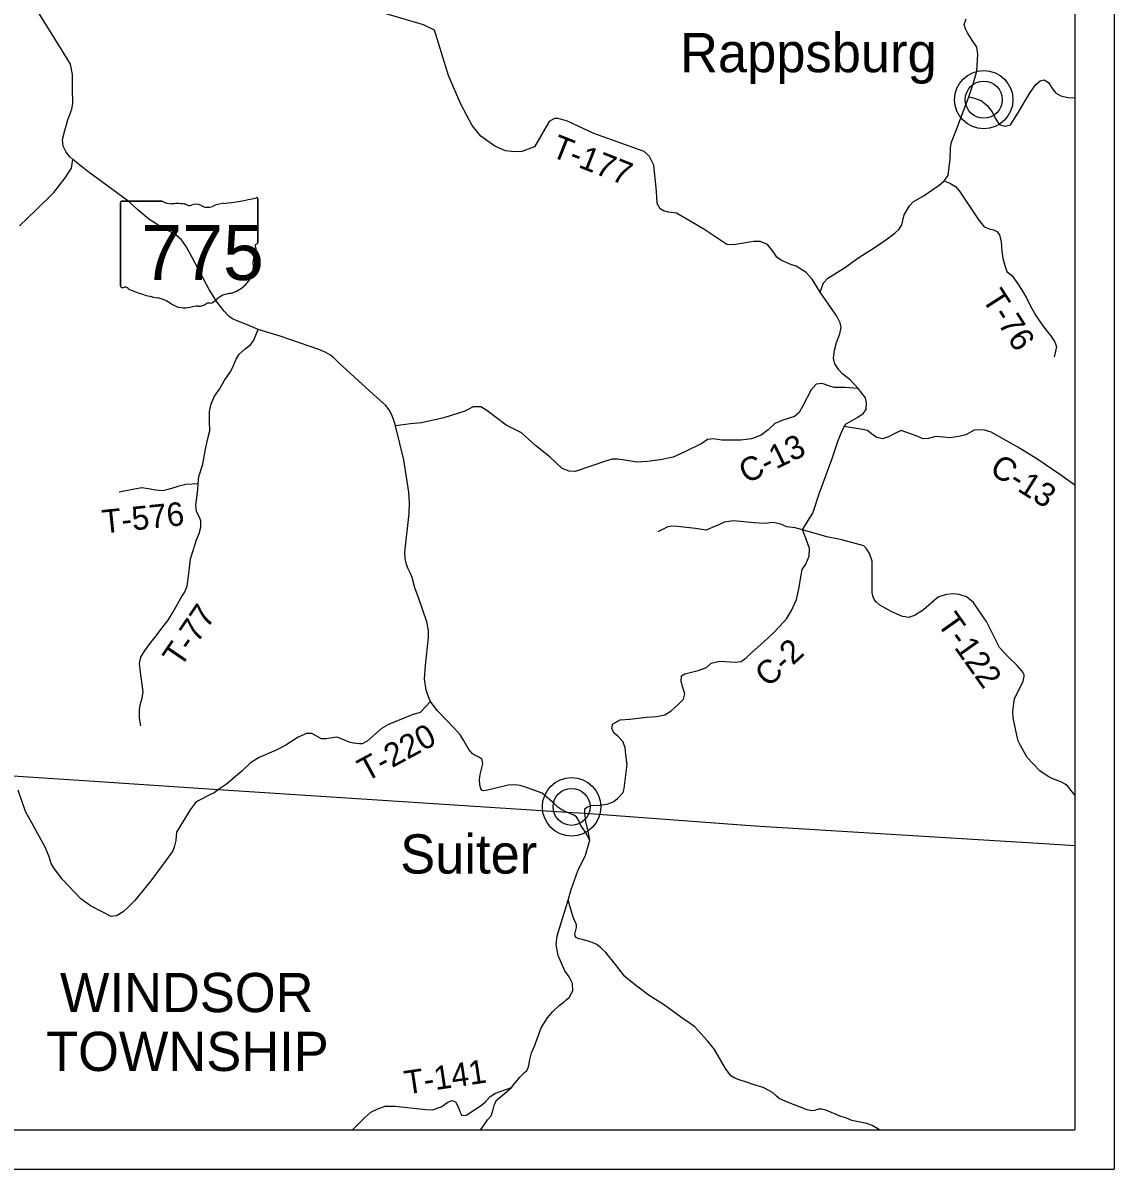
# Model space of a CAD drawing. Extents: x -6.4 to 34, y -1.2 to 22.
# Drawn here: x 6.219 to 9, y 14 to 16.922 of the extents above; entities that cross this region are included whole.
import ezdxf

# ---------------------------------------------------------------- set-up
doc = ezdxf.new("R2010")
doc.units = 0
for name, color, linetype in [('GM_X_County_Road', 7, 'Continuous'), ('GM_X_County_ROW', 7, 'Continuous'), ('GM_X_Minor_Lake', 7, 'Continuous'), ('GM_X_Minor_River', 7, 'Continuous'), ('GM_X_Minor_River_Text', 7, 'Continuous'), ('GM_X_Township', 7, 'Continuous'), ('GM_X_Township_Road', 7, 'Continuous'), ('GM_X_Township_ROW', 7, 'Continuous'), ('GM_X_Township_Subdivision', 7, 'Continuous'), ('GM_X_Township_Subdivision_Text', 7, 'Continuous'), ('GM_X_Township_Text', 7, 'Continuous')]:
    doc.layers.add(name, color=color, linetype=linetype)

msp = doc.modelspace()

# ---------------------------------------------------------------- linework, layer by layer
at = {"layer": 'GM_X_County_Road'}
for centre, radius in [((8.6678, 16.7259), 0.0744), ((8.6678, 16.7259), 0.0472), ((7.6173, 14.9233), 0.0744), ((7.6173, 14.9233), 0.0472)]:
    msp.add_circle(centre, radius, dxfattribs=at)
at = {"layer": 'GM_X_County_ROW'}
for p, q in [((6.4677, 16.4637), (6.4677, 16.2511)), ((6.5736, 16.4673), (6.4711, 16.4673)), ((6.8177, 16.3614), (6.8177, 16.4726)), ((6.8177, 16.3614), (6.8177, 16.3614))]:
    msp.add_line(p, q, dxfattribs=at)
for centre, major_axis, start_param, end_param in [((6.4717, 16.4641), (0.00406, 0), 1.712693, 3.28349), ((6.598, 16.492), (0.0393, 0), 4.042523, 4.731795), ((6.6111, 16.348), (0.1412, 0), 1.404758, 1.657858), ((6.6431, 16.4652), (0.0113, 0), 3.836095, 5.185415), ((6.6598, 16.4407), (0.0236, 0), 0.950623, 2.079405), ((6.6903, 16.4744), (0.0284, 0), 4.081561, 5.145723), ((6.7404, 16.4024), (0.0747, 0), 1.699011, 2.107814), ((6.693, 16.7571), (0.3713, 0), 4.814394, 5.042369), ((6.8139, 16.4731), (0.0039, 0), 6.141152, 7.989035), ((6.8136, 16.361), (0.00417, 0), 5.05454, 6.418171), ((6.8168, 16.3532), (0.00603, 0), 1.883978, 3.671073), ((6.7785, 16.3392), (0.0362, 0), 5.934695, 6.695948), ((6.7138, 16.3007), (0.0929, 0), 5.101752, 6.440018), ((6.8317, 16.3149), (0.0263, 0), 2.387724, 3.262537), ((6.4717, 16.2506), (0.00409, 0), 3.00124, 4.508301), ((6.4723, 16.2724), (0.0312, 0), 4.665946, 4.897461), ((6.4787, 16.2388), (0.0113, 0), 0.519207, 1.627899), ((6.6209, 16.4298), (0.2681, 0), 4.195997, 4.488961), ((6.5409, 16.1556), (0.0839, 0), 0.823519, 1.323587), ((6.6886, 16.2305), (0.03, 0), 4.937069, 5.64225), ((6.753, 16.1914), (0.0509, 0), 1.647645, 2.488434), ((6.6317, 16.2378), (0.0532, 0), 4.026481, 4.996735), ((6.6624, 16.1643), (0.0437, 0), 1.495662, 1.94098), ((6.6663, 16.2219), (0.0284, 0), 4.691044, 5.507374), ((6.692, 16.2013), (0.00798, 0), 1.147584, 2.315152)]:
    msp.add_ellipse(centre, major_axis=major_axis, ratio=0.8, start_param=start_param, end_param=end_param, dxfattribs=at)
at = {"layer": 'GM_X_Minor_Lake'}
msp.add_lwpolyline([(8.4009, 14.1), (8.3976, 14.1026), (8.3838, 14.1109), (8.3699, 14.1162), (8.3488, 14.1206), (8.3314, 14.1241), (8.3183, 14.1298), (8.3022, 14.1351), (8.265, 14.1498), (8.2545, 14.1523), (8.2458, 14.1529), (8.237, 14.1494), (8.2297, 14.1488), (8.2181, 14.1514), (8.1633, 14.1722), (8.1468, 14.1798), (8.1394, 14.1857), (8.1294, 14.1951), (8.1197, 14.2003), (8.1055, 14.2079), (8.0826, 14.2149), (8.0634, 14.2212), (8.0442, 14.2274), (8.0334, 14.2314), (8.0233, 14.2378), (8.0098, 14.2567), (7.9815, 14.3046), (7.9639, 14.3271), (7.9466, 14.3453), (7.9315, 14.3628), (7.917, 14.3731), (7.898, 14.3857), (7.8538, 14.4177), (7.8154, 14.4422), (7.7835, 14.4666), (7.7586, 14.4858), (7.7519, 14.4917), (7.7292, 14.5212), (7.7043, 14.5518), (7.6914, 14.5651), (7.6817, 14.5722), (7.6701, 14.5778), (7.6592, 14.5807), (7.6453, 14.5849), (7.6347, 14.5867), (7.6291, 14.5899), (7.6266, 14.5945), (7.6256, 14.5987), (7.6269, 14.6059), (7.6302, 14.6157), (7.63, 14.6229), (7.6214, 14.6421), (7.6086, 14.6853), (7.6165, 14.7124), (7.6334, 14.7598), (7.6525, 14.8003), (7.6635, 14.8385), (7.6525, 14.8585), (7.6413, 14.8754), (7.6351, 14.8892), (7.6295, 14.8976), (7.623, 14.9024), (7.6051, 14.9095), (7.5949, 14.9136), (7.5825, 14.9226), (7.5738, 14.9311), (7.5426, 14.9578), (7.5, 14.9733), (7.4861, 14.9778), (7.4732, 14.9793), (7.4558, 14.9786), (7.4173, 14.9694), (7.3997, 14.9653), (7.3936, 14.9643), (7.3895, 14.9652), (7.3858, 14.9695), (7.3838, 14.9805), (7.383, 14.9923), (7.3845, 15.0059), (7.3909, 15.0327), (7.3907, 15.0392), (7.3886, 15.0449), (7.3811, 15.0497), (7.3688, 15.0561), (7.3636, 15.0596), (7.3551, 15.0697), (7.3418, 15.0936), (7.3341, 15.106), (7.3191, 15.1234), (7.2748, 15.169), (7.2576, 15.1922), (7.2544, 15.1999), (7.2463, 15.221), (7.2421, 15.25), (7.2446, 15.2837), (7.2526, 15.3548), (7.253, 15.373), (7.2483, 15.3948), (7.2283, 15.4542), (7.2188, 15.4791), (7.216, 15.4887), (7.2112, 15.5078), (7.2065, 15.5178), (7.2008, 15.5301), (7.1966, 15.5408), (7.1932, 15.5561), (7.1921, 15.5728), (7.2035, 15.6712), (7.2046, 15.6974), (7.2023, 15.7255), (7.1894, 15.8075), (7.1682, 15.8942), (7.1644, 15.9087), (7.158, 15.9244), (7.1523, 15.9356), (7.1427, 15.9472), (7.1128, 15.9746), (7.0243, 16.0547), (7.0114, 16.068), (7.0029, 16.0746), (6.9906, 16.0818), (6.973, 16.0895), (6.8742, 16.1228), (6.8186, 16.1402), (6.7931, 16.1515), (6.7605, 16.1641), (6.7533, 16.1673), (6.7444, 16.1733), (6.7319, 16.1869), (6.7132, 16.2105), (6.6932, 16.2422), (6.6431, 16.3361), (6.6329, 16.3546), (6.6235, 16.3689), (6.6064, 16.3834), (6.572, 16.4006), (6.5396, 16.4212), (6.5129, 16.4439), (6.5007, 16.4552), (6.4867, 16.4678), (6.3844, 16.543), (6.3462, 16.5736), (6.3388, 16.5806), (6.3293, 16.5922), (6.3217, 16.6072), (6.3199, 16.6247), (6.3255, 16.6474), (6.3338, 16.6749), (6.3436, 16.7015), (6.3459, 16.7167), (6.345, 16.7535), (6.345, 16.7904), (6.3402, 16.8165), (6.3215, 16.8466), (6.2435, 16.9728)], dxfattribs=at)
at = {"layer": 'GM_X_Minor_River'}
for points in [[(7.6514, 14.9162), (7.6514, 14.9181), (7.6562, 14.9229), (7.6669, 14.9268), (7.6883, 14.928), (7.7082, 14.9299), (7.7248, 14.9367), (7.7347, 14.9448), (7.7484, 14.96), (7.751, 14.9704), (7.7543, 14.9907), (7.7591, 15.0309), (7.7554, 15.0556), (7.754, 15.0746), (7.7476, 15.0902), (7.7356, 15.1032), (7.7258, 15.1109), (7.7201, 15.1223), (7.7214, 15.1316), (7.7217, 15.1344), (7.7411, 15.145), (7.7654, 15.1464), (7.8083, 15.1518), (7.8337, 15.1536), (7.8553, 15.1581), (7.8709, 15.1682), (7.8881, 15.1833), (7.9022, 15.1977), (7.9061, 15.2114), (7.9012, 15.2277), (7.8964, 15.2426), (7.8972, 15.257), (7.9063, 15.2626), (7.9398, 15.2708), (7.961, 15.2787), (7.9732, 15.2893), (7.9956, 15.2945), (8.0354, 15.292), (8.0495, 15.2938), (8.0624, 15.3032), (8.0769, 15.3165), (8.1078, 15.3448), (8.1306, 15.3652), (8.1482, 15.3837), (8.165, 15.4026), (8.1776, 15.4234), (8.1903, 15.4519), (8.1976, 15.4822), (8.2016, 15.5095), (8.2047, 15.5281), (8.2143, 15.5417), (8.2231, 15.5626), (8.224, 15.582), (8.2143, 15.6078), (8.2057, 15.6291), (8.2229, 15.6575), (8.2325, 15.6723), (8.2491, 15.7235), (8.281, 15.8091), (8.2972, 15.8573), (8.3041, 15.8755), (8.3123, 15.8927), (8.3172, 15.8993), (8.3465, 15.917), (8.3602, 15.9257), (8.3682, 15.9363), (8.369, 15.9534), (8.3661, 15.9663), (8.3477, 15.9897), (8.3277, 16.0117), (8.3084, 16.0258), (8.2982, 16.0369), (8.2881, 16.0522), (8.2847, 16.0674), (8.2871, 16.0875), (8.2929, 16.1068), (8.3014, 16.1292), (8.3041, 16.1451), (8.3019, 16.1573), (8.2937, 16.1744), (8.2512, 16.235), (8.2593, 16.2589), (8.2707, 16.2706), (8.313, 16.297), (8.3491, 16.3234), (8.391, 16.3501), (8.4184, 16.3686), (8.4409, 16.3859), (8.4519, 16.3958), (8.4588, 16.4071), (8.465, 16.4325), (8.4784, 16.4552), (8.4883, 16.4654), (8.5157, 16.482), (8.5378, 16.4971), (8.5545, 16.508), (8.5656, 16.5175), (8.5671, 16.5193), (8.5774, 16.5322), (8.5822, 16.574), (8.5835, 16.6039), (8.5859, 16.6172), (8.5963, 16.646), (8.6298, 16.7328), (8.6421, 16.7688), (8.6502, 16.7984), (8.6531, 16.8421), (8.6502, 16.8599), (8.637, 16.8805), (8.6265, 16.8961), (8.6209, 16.9068), (8.6179, 16.9174), (8.6233, 16.9322)], [(8.6298, 16.7328), (8.6411, 16.7305), (8.6612, 16.7236), (8.6763, 16.7113), (8.6891, 16.6946), (8.6954, 16.6824), (8.703, 16.6694), (8.7086, 16.6614), (8.7222, 16.6583), (8.7363, 16.6616), (8.7481, 16.6802), (8.7589, 16.6987), (8.7738, 16.7226), (8.7864, 16.7442), (8.8002, 16.7642), (8.8116, 16.7737), (8.8219, 16.7767), (8.8328, 16.7694), (8.8411, 16.7564), (8.8505, 16.7431), (8.8641, 16.7358), (8.8819, 16.7315), (8.9, 16.7302)], [(6.2103, 16.4042), (6.2518, 16.4439), (6.2979, 16.4889), (6.3266, 16.5267), (6.343, 16.5513), (6.3462, 16.5736)], [(8.3477, 15.9897), (8.3135, 15.992), (8.2862, 15.9918), (8.2726, 15.9968), (8.2559, 16.0026), (8.2404, 16.0007), (8.2278, 15.986), (8.2071, 15.9455), (8.1971, 15.9284), (8.1857, 15.9186), (8.1561, 15.9089), (8.1352, 15.9003), (8.118, 15.884), (8.1009, 15.8704), (8.0762, 15.8618), (8.0485, 15.8582), (8.0181, 15.8583), (8.0007, 15.858), (7.9791, 15.8612), (7.9639, 15.8594), (7.9491, 15.8496), (7.9046, 15.827), (7.8765, 15.815), (7.8431, 15.8076), (7.8104, 15.8035), (7.7835, 15.8022), (7.7528, 15.8069), (7.7342, 15.8092), (7.7206, 15.8093), (7.7035, 15.8041), (7.6264, 15.7779), (7.6108, 15.7791), (7.5934, 15.786), (7.5629, 15.815), (7.5255, 15.8445), (7.4897, 15.8769), (7.4503, 15.8965), (7.4013, 15.9332), (7.3858, 15.9427), (7.3664, 15.9428), (7.3451, 15.9319), (7.292, 15.9151), (7.2346, 15.9025), (7.2066, 15.8996), (7.1682, 15.8942)], [(8.9, 15.7435), (8.864, 15.7686), (8.8054, 15.8084), (8.7551, 15.8398), (8.7143, 15.8628), (8.6871, 15.8781), (8.6674, 15.8843), (8.6432, 15.8836), (8.6219, 15.8716), (8.604, 15.8671), (8.582, 15.8642), (8.5642, 15.8658), (8.5456, 15.8674), (8.527, 15.8626), (8.5137, 15.8615), (8.4956, 15.8692), (8.4577, 15.8823), (8.441, 15.8748), (8.425, 15.8661), (8.4102, 15.8613), (8.3955, 15.8648), (8.3819, 15.8743), (8.3713, 15.8827), (8.3584, 15.8855), (8.3123, 15.8927)], [(7.6635, 14.8385), (7.6593, 14.861), (7.6534, 14.8861), (7.6512, 14.9069), (7.6514, 14.9162)], [(7.3864, 14.1), (7.3864, 14.1006), (7.3949, 14.1131), (7.4029, 14.1252), (7.412, 14.1358), (7.4178, 14.1521), (7.4209, 14.1654), (7.4267, 14.1764), (7.4335, 14.1817), (7.4646, 14.2081), (7.4705, 14.2157), (7.4778, 14.2247), (7.4862, 14.2349), (7.4909, 14.2398), (7.497, 14.2463), (7.503, 14.2516), (7.5077, 14.2602), (7.5093, 14.2682), (7.5111, 14.2796), (7.5152, 14.296), (7.5226, 14.3137), (7.5396, 14.3597), (7.556, 14.3851), (7.5694, 14.4013), (7.5854, 14.4168), (7.5983, 14.4266), (7.6038, 14.4314), (7.6109, 14.4376), (7.6208, 14.4543), (7.6194, 14.4729), (7.6112, 14.49), (7.6003, 14.5056), (7.5831, 14.5441), (7.5779, 14.5726), (7.5803, 14.5942), (7.6086, 14.6853)]]:
    msp.add_lwpolyline(points, dxfattribs=at)
at = {"layer": 'GM_X_Minor_River_Text'}
for points in [[(8.2512, 16.235), (8.2308, 16.2687), (8.2148, 16.2852), (8.1898, 16.3013), (8.1763, 16.3061), (8.1522, 16.3163), (8.1407, 16.3247), (8.1315, 16.3389), (8.1167, 16.3569), (8.098, 16.3642), (8.0811, 16.3646), (8.0303, 16.3555), (8.0129, 16.3568), (7.9542, 16.3957), (7.8844, 16.4364), (7.864, 16.4393), (7.8512, 16.4427), (7.8433, 16.4478), (7.8355, 16.4615), (7.834, 16.4926), (7.8266, 16.5591), (7.8159, 16.5808), (7.8022, 16.5939), (7.6744, 16.6396), (7.607, 16.6712), (7.5835, 16.6779), (7.5737, 16.6777), (7.56, 16.6703), (7.5226, 16.6059), (7.4902, 16.5934), (7.4716, 16.5929), (7.4492, 16.5951), (7.4217, 16.607), (7.3858, 16.6326), (7.3642, 16.6601), (7.3352, 16.7144), (7.3038, 16.7871), (7.2682, 16.9031), (7.24, 16.917), (7.1241, 16.9504)], [(8.5671, 16.5193), (8.5834, 16.512), (8.5955, 16.5048), (8.6064, 16.4929), (8.6549, 16.4186), (8.6692, 16.4019), (8.6813, 16.3969), (8.6931, 16.3945), (8.701, 16.3895), (8.7078, 16.3812), (8.7122, 16.3637), (8.714, 16.3401), (8.7165, 16.3222), (8.7217, 16.3032), (8.7266, 16.2876), (8.7402, 16.2769), (8.7545, 16.2564), (8.7642, 16.2419), (8.7766, 16.2205), (8.7871, 16.1992), (8.8003, 16.1756), (8.8108, 16.1604), (8.8232, 16.1425), (8.8402, 16.1215), (8.8492, 16.1081), (8.8529, 16.0967), (8.8498, 16.0804), (8.8472, 16.0706)], [(6.5195, 15.1301), (6.516, 15.1495), (6.5158, 15.1689), (6.5181, 15.1833), (6.5231, 15.2003), (6.5251, 15.2163), (6.519, 15.2668), (6.516, 15.2885), (6.5192, 15.3048), (6.5287, 15.3203), (6.5448, 15.3419), (6.5589, 15.3593), (6.5727, 15.3786), (6.5895, 15.399), (6.6021, 15.4202), (6.6128, 15.4399), (6.622, 15.4566), (6.6304, 15.4698), (6.6374, 15.4861), (6.6401, 15.5051), (6.6433, 15.5324), (6.6461, 15.5556), (6.653, 15.5764), (6.6615, 15.6037), (6.6681, 15.6204), (6.6723, 15.6363), (6.6724, 15.6527), (6.6683, 15.6637), (6.6616, 15.6763), (6.6598, 15.6934), (6.6618, 15.712), (6.6645, 15.7313), (6.6658, 15.7464), (6.6674, 15.7651), (6.6778, 15.7966), (6.6844, 15.8353), (6.6903, 15.8626), (6.6949, 15.8819), (6.6947, 15.9055), (6.6948, 15.9309), (6.6987, 15.9503), (6.7068, 15.97), (6.7198, 15.9882), (6.7321, 16.0094), (6.7473, 16.0309), (6.7535, 16.0427), (6.7623, 16.0647), (6.7704, 16.0775), (6.7856, 16.0904), (6.7989, 16.1006), (6.8066, 16.1108), (6.8186, 16.1402)], [(6.6658, 15.7464), (6.6339, 15.7451), (6.616, 15.7407), (6.6039, 15.7369), (6.5883, 15.7325), (6.5758, 15.7287), (6.5565, 15.7303), (6.5432, 15.7334), (6.522, 15.7362), (6.4988, 15.7321), (6.4643, 15.7255)], [(8.2057, 15.6291), (8.1875, 15.6345), (8.1659, 15.6369), (8.1508, 15.6438), (8.1311, 15.6477), (8.1087, 15.6456), (8.0825, 15.6476), (8.0302, 15.652), (8.0063, 15.6487), (7.9942, 15.6427), (7.9759, 15.6352), (7.9607, 15.6285), (7.9334, 15.6332), (7.8872, 15.6383), (7.8732, 15.6384), (7.8629, 15.6369), (7.8375, 15.6242)], [(8.6931, 15.3598), (8.6747, 15.396), (8.67, 15.4028), (8.6413, 15.4444), (8.6241, 15.459), (8.6055, 15.4646), (8.591, 15.4665), (8.5728, 15.4647), (8.5536, 15.4587), (8.5471, 15.4543), (8.5143, 15.4251), (8.4934, 15.4119), (8.477, 15.4063), (8.4678, 15.4073), (8.4611, 15.4083), (8.4336, 15.4206), (8.403, 15.4376), (8.3934, 15.4461), (8.3889, 15.4522), (8.3854, 15.4614), (8.3838, 15.4699), (8.3835, 15.5497), (8.3764, 15.5689), (8.3681, 15.5823), (8.3618, 15.5884), (8.3065, 15.6039), (8.268, 15.6113), (8.2057, 15.6291)], [(8.9, 14.9533), (8.8982, 14.9554), (8.8936, 14.9616), (8.8875, 14.9692), (8.8825, 14.9761), (8.8756, 14.9815), (8.8661, 14.9864), (8.8577, 14.9899), (8.8439, 14.9948), (8.8339, 14.9994), (8.8217, 15.0075), (8.8106, 15.0151), (8.7786, 15.0487), (8.7613, 15.0796), (8.7557, 15.092), (8.7531, 15.1021), (8.7426, 15.1499), (8.7418, 15.1655), (8.7444, 15.1875), (8.7463, 15.1989), (8.7684, 15.2438), (8.7709, 15.2561), (8.7706, 15.2601), (8.7681, 15.2652), (8.765, 15.2701), (8.7534, 15.2834), (8.7281, 15.3077), (8.7083, 15.3299), (8.6931, 15.3598)], [(7.2576, 15.1922), (7.2316, 15.1636), (7.2114, 15.1576), (7.1505, 15.1334), (7.1325, 15.1229), (7.0966, 15.0905), (7.0839, 15.0843), (7.0769, 15.0839), (7.0613, 15.0857), (7.0506, 15.0883), (7.0265, 15.0987), (7.0189, 15.1008), (7.0127, 15.1002), (6.992, 15.0966), (6.9798, 15.0967), (6.9549, 15.1101), (6.9416, 15.1102), (6.9204, 15.1011), (6.8894, 15.0804), (6.8646, 15.0675), (6.8212, 15.0494), (6.7988, 15.0354), (6.7771, 15.0139), (6.7374, 14.981), (6.7178, 14.9672), (6.7169, 14.9666)], [(6.7169, 14.9666), (6.7066, 14.9593), (6.6986, 14.9553), (6.6639, 14.9382), (6.6579, 14.9325), (6.645, 14.9154), (6.61, 14.8585), (6.6088, 14.8379), (6.6042, 14.8206), (6.6006, 14.8116), (6.5817, 14.784), (6.5449, 14.7349), (6.5044, 14.6842), (6.4969, 14.6768), (6.4889, 14.669), (6.4744, 14.6558), (6.4573, 14.6456), (6.4435, 14.6436), (6.3912, 14.6714), (6.3663, 14.6888), (6.32, 14.7378), (6.2989, 14.7663), (6.2911, 14.7786), (6.2858, 14.7963), (6.2757, 14.8202), (6.2323, 14.8996), (6.2305, 14.9025), (6.2253, 14.9114), (6.207, 14.9657)], [(7.0591, 14.1), (7.0726, 14.1139), (7.0901, 14.1317), (7.1057, 14.1449), (7.1232, 14.1532), (7.1418, 14.1603), (7.1676, 14.1606), (7.2461, 14.1522), (7.2631, 14.1506), (7.2851, 14.1585), (7.3015, 14.1705), (7.3129, 14.1747), (7.3212, 14.1716), (7.3284, 14.159), (7.3332, 14.1453), (7.3377, 14.1365), (7.3495, 14.1376), (7.3685, 14.1504), (7.3849, 14.161), (7.3971, 14.1708), (7.4097, 14.1852), (7.4237, 14.1931), (7.4646, 14.2081)]]:
    msp.add_lwpolyline(points, dxfattribs=at)
at = {"layer": 'GM_X_Township'}
for p, q in [((9, 21), (9, 14)), ((8.9, 20.9), (8.9, 14.1)), ((2.1, 14.1), (8.9, 14.1)), ((2, 14), (9, 14))]:
    msp.add_line(p, q, dxfattribs=at)
at = {"layer": 'GM_X_Township_Road'}
for p, q in [((6.4677, 16.2511), (6.4677, 16.4637)), ((6.4711, 16.4673), (6.5736, 16.4673)), ((6.8177, 16.4726), (6.8177, 16.3614)), ((6.815, 16.3578), (6.815, 16.3578))]:
    msp.add_line(p, q, dxfattribs=at)
for centre, major_axis, start_param, end_param in [((6.4717, 16.4641), (0.00406, 0), 1.712693, 3.28349), ((6.598, 16.492), (0.0393, 0), 4.042523, 4.731795), ((6.6111, 16.348), (0.1412, 0), 1.404758, 1.657858), ((6.6431, 16.4652), (0.0113, 0), 3.836095, 5.185415), ((6.6598, 16.4407), (0.0236, 0), 0.950623, 2.079405), ((6.6903, 16.4744), (0.0284, 0), 4.081561, 5.145723), ((6.7404, 16.4024), (0.0747, 0), 1.699011, 2.107814), ((6.693, 16.7571), (0.3713, 0), 4.814394, 5.042369), ((6.8139, 16.4731), (0.0039, 0), 6.141152, 7.989035), ((6.8136, 16.361), (0.00417, 0), 5.05454, 6.418171), ((6.8168, 16.3532), (0.00603, 0), 1.883978, 3.671073), ((6.7785, 16.3392), (0.0362, 0), 5.934695, 6.695948), ((6.7138, 16.3007), (0.0929, 0), 5.101752, 6.440018), ((6.8317, 16.3149), (0.0263, 0), 2.387724, 3.262537), ((6.4717, 16.2506), (0.00409, 0), 3.00124, 4.508301), ((6.4723, 16.2724), (0.0312, 0), 4.665946, 4.897461), ((6.4787, 16.2388), (0.0113, 0), 0.519207, 1.627899), ((6.6209, 16.4298), (0.2681, 0), 4.195997, 4.488961), ((6.5409, 16.1556), (0.0839, 0), 0.823519, 1.323587), ((6.6886, 16.2305), (0.03, 0), 4.937069, 5.64225), ((6.753, 16.1914), (0.0509, 0), 1.647645, 2.488434), ((6.6317, 16.2378), (0.0532, 0), 4.026481, 4.996735), ((6.6624, 16.1643), (0.0437, 0), 1.495662, 1.94098), ((6.6663, 16.2219), (0.0284, 0), 4.691044, 5.507374), ((6.692, 16.2013), (0.00798, 0), 1.147584, 2.315152)]:
    msp.add_ellipse(centre, major_axis=major_axis, ratio=0.8, start_param=start_param, end_param=end_param, dxfattribs=at)
at = {"layer": 'GM_X_Township_ROW'}
msp.add_lwpolyline([(4.5386, 14.1), (4.5516, 14.3018), (4.5837, 14.7973), (4.6039, 15.1106), (4.7025, 15.1042), (4.9433, 15.0884), (5.1541, 15.0746), (5.2376, 15.0692), (5.6728, 15.0407), (6.0364, 15.013), (6.1929, 15.0025), (6.375, 14.9903), (6.7178, 14.9672), (7.6051, 14.9095), (7.6512, 14.9069), (8.0847, 14.8753), (8.8343, 14.8293), (8.9, 14.8252)], dxfattribs=at)

# ---------------------------------------------------------------- texts
at = {"layer": 'GM_X_County_Road'}
for s, p in [('Rappsburg', (7.8938, 16.7959)), ('Suiter', (7.1805, 14.7533))]:
    msp.add_text(s, height=0.1, dxfattribs=at).set_placement(p)
at = {"layer": 'GM_X_County_ROW'}
msp.add_text('775', height=0.14004, dxfattribs=at).set_placement((6.5207, 16.2661))
at = {"layer": 'GM_X_Township_Subdivision'}
for s, rotation, p in [('T-177', 338.4048, (7.5618, 16.5825)), ('T-76', 302.7482, (8.6617, 16.2187)), ('T-576', 5.9274, (6.4239, 15.62)), ('T-77', 55.7742, (6.6206, 15.2759)), ('T-122', 305.3744, (8.547, 15.3914)), ('T-220', 28.4319, (7.0932, 14.9858)), ('T-141', 8.4315, (7.1957, 14.1902))]:
    msp.add_text(s, height=0.06, rotation=rotation, dxfattribs=at).set_placement(p)
at = {"layer": 'GM_X_Township_Subdivision_Text'}
for s, p in [('WINDSOR', (6.3133, 14.4)), ('TOWNSHIP', (6.2778, 14.25))]:
    msp.add_text(s, height=0.1, dxfattribs=at).set_placement(p)
at = {"layer": 'GM_X_Township_Text'}
for s, rotation, p in [('C-13', 25.8992, (8.0624, 15.7461)), ('C-13', 327.8091, (8.6795, 15.7753)), ('C-2', 42.2396, (8.1183, 15.2258))]:
    msp.add_text(s, height=0.06, rotation=rotation, dxfattribs=at).set_placement(p)

doc.saveas('drawing.dxf')
